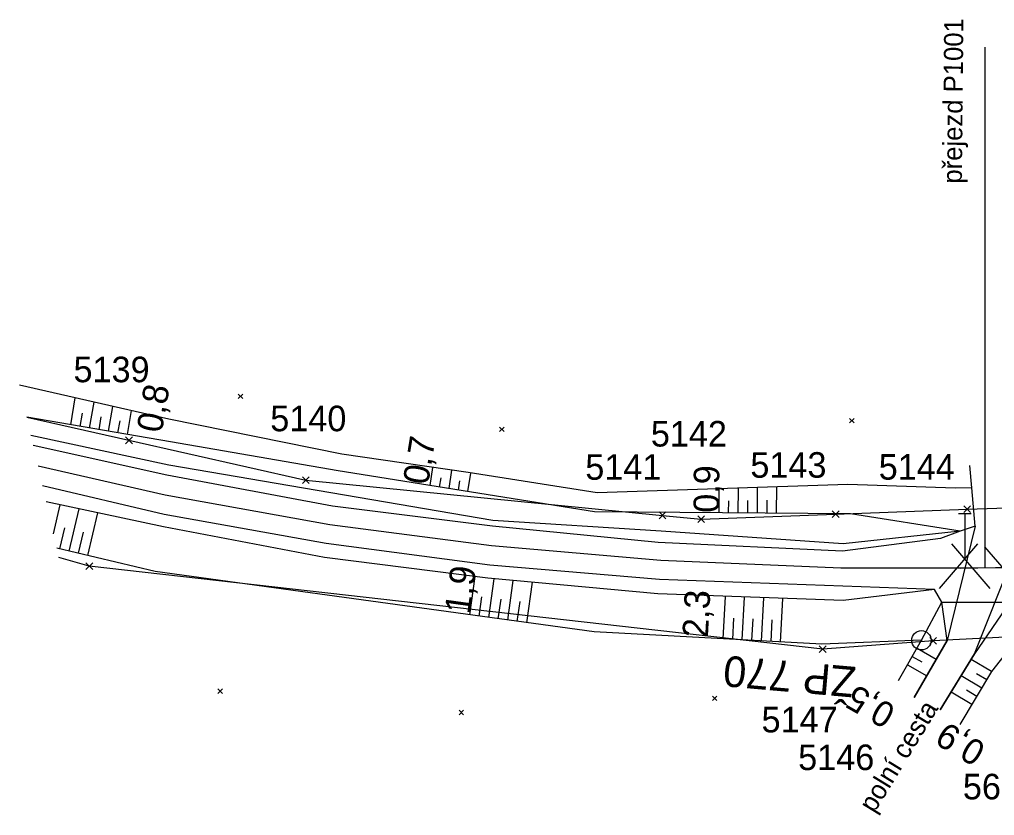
# Model space of a CAD drawing. Extents: x -805730 to -804640, y -1150889 to -1150366.
# Drawn here: x -805497.5 to -805421.3, y -1150709.2 to -1150646.9 of the extents above; entities that cross this region are included whole.
import ezdxf

# ---------------------------------------------------------------- set-up
doc = ezdxf.new("R2010")
doc.units = 0
for name, color, linetype in [('0381KM032-037P - Vrstva 1', 7, 'Continuous'), ('0381KM032-037P - Vrstva 19', 7, 'Continuous'), ('0381KM032-037P - Vrstva 4', 7, 'Continuous'), ('0381KM032-037P - Vrstva 48', 7, 'Continuous'), ('0381KM032-037P - Vrstva 49', 7, 'Continuous'), ('0381KM032-037P - Vrstva 51', 7, 'Continuous'), ('szdc - hran DP', 7, 'Continuous'), ('szdc - szdc_cislo', 7, 'Continuous'), ('szdc - szdc_krizek', 7, 'Continuous'), ('vyt_sit - stávající', 7, 'Continuous')]:
    doc.layers.add(name, color=color, linetype=linetype)

msp = doc.modelspace()

# ---------------------------------------------------------------- linework, layer by layer
at = {"layer": '0381KM032-037P - Vrstva 1'}
msp.add_lwpolyline([(-805364.564, -1150682.932), (-805366.036, -1150683.288), (-805378.364, -1150685.708), (-805390.905, -1150687.547), (-805419.964, -1150689.775), (-805423.956, -1150689.798), (-805433.29, -1150689.8), (-805447.38, -1150689.21), (-805460.61, -1150688.07), (-805473.24, -1150686.41), (-805486.12, -1150684.11), (-805496.07, -1150681.84)], dxfattribs=at)
at = {"layer": '0381KM032-037P - Vrstva 19'}
msp.add_line((-805425.408, -1150692.468), (-805420.073, -1150692.467), dxfattribs=at)
at = {"layer": '0381KM032-037P - Vrstva 4'}
for p, q in [((-805421.995, -1150689.771), (-805421.995, -1150649.075)), ((-805423.106, -1150685.551), (-805424.106, -1150685.551)), ((-805423.606, -1150685.551), (-805423.606, -1150689.051)), ((-805422.606, -1150687.901), (-805425.606, -1150691.401)), ((-805421.606, -1150691.401), (-805424.606, -1150687.901)), ((-805422.051, -1150688.145), (-805419.051, -1150691.645)), ((-805423.956, -1150689.798), (-805419.82, -1150689.74))]:
    msp.add_line(p, q, dxfattribs=at)
for points in [[(-805485.852, -1150681.76), (-805496.622, -1150679.425)], [(-805423.968, -1150686.92), (-805425.507, -1150687.489), (-805433.167, -1150688.486), (-805447.577, -1150687.793), (-805460.544, -1150686.523), (-805473.033, -1150684.969), (-805486.003, -1150682.535), (-805496.44, -1150680.221)], [(-805423.968, -1150686.92), (-805433.105, -1150687.911), (-805447.337, -1150686.911), (-805460.493, -1150686.088), (-805485.852, -1150681.76)], [(-805425.977, -1150691.468), (-805433.128, -1150691.222), (-805447.474, -1150690.705), (-805460.736, -1150689.572), (-805473.542, -1150687.873), (-805486.195, -1150685.623), (-805495.723, -1150683.361)], [(-805425.408, -1150692.468), (-805425.977, -1150691.468), (-805433.111, -1150692.346), (-805447.611, -1150691.816), (-805460.898, -1150690.591), (-805473.672, -1150688.976), (-805486.257, -1150686.575), (-805495.432, -1150684.633)]]:
    msp.add_lwpolyline(points, dxfattribs=at)
at = {"layer": '0381KM032-037P - Vrstva 48'}
for p, q in [((-805493.516, -1150678.599), (-805493.154, -1150676.492)), ((-805492.038, -1150678.853), (-805491.689, -1150676.823)), ((-805492.777, -1150678.726), (-805492.599, -1150677.692)), ((-805490.56, -1150679.107), (-805490.224, -1150677.155)), ((-805489.082, -1150679.361), (-805488.759, -1150677.486)), ((-805491.299, -1150678.98), (-805491.128, -1150677.985)), ((-805489.821, -1150679.234), (-805489.656, -1150678.277)), ((-805465.411, -1150683.343), (-805465.185, -1150681.938)), ((-805463.93, -1150683.582), (-805463.701, -1150682.155)), ((-805462.45, -1150683.82), (-805462.217, -1150682.374)), ((-805464.671, -1150683.462), (-805464.557, -1150682.754)), ((-805463.19, -1150683.701), (-805463.074, -1150682.982)), ((-805442.816, -1150685.486), (-805442.802, -1150683.603)), ((-805441.316, -1150685.497), (-805441.302, -1150683.554)), ((-805439.816, -1150685.508), (-805439.801, -1150683.505)), ((-805438.316, -1150685.519), (-805438.301, -1150683.457)), ((-805442.066, -1150685.491), (-805442.059, -1150684.535)), ((-805440.566, -1150685.502), (-805440.559, -1150684.516)), ((-805439.066, -1150685.514), (-805439.059, -1150684.497)), ((-805494.863, -1150687.121), (-805494.328, -1150684.869)), ((-805493.641, -1150688.469), (-805492.86, -1150685.181)), ((-805492.182, -1150688.816), (-805491.392, -1150685.492)), ((-805494.371, -1150688.296), (-805493.982, -1150686.66)), ((-805492.911, -1150688.642), (-805492.519, -1150686.989)), ((-805462.306, -1150693.457), (-805461.892, -1150690.465)), ((-805460.82, -1150693.663), (-805460.401, -1150690.636)), ((-805459.334, -1150693.868), (-805458.906, -1150690.775)), ((-805457.848, -1150694.074), (-805457.411, -1150690.913)), ((-805461.563, -1150693.56), (-805461.355, -1150692.059)), ((-805460.077, -1150693.766), (-805459.865, -1150692.235)), ((-805442.496, -1150695.345), (-805442.316, -1150692.013)), ((-805440.998, -1150695.425), (-805440.817, -1150692.068)), ((-805439.5, -1150695.506), (-805439.318, -1150692.123)), ((-805438.003, -1150695.587), (-805437.819, -1150692.178)), ((-805458.591, -1150693.971), (-805458.375, -1150692.407)), ((-805441.747, -1150695.385), (-805441.657, -1150693.713)), ((-805440.249, -1150695.466), (-805440.158, -1150693.781)), ((-805438.751, -1150695.546), (-805438.66, -1150693.848)), ((-805427.337, -1150696.056), (-805425.831, -1150696.919)), ((-805427.71, -1150696.707), (-805426.958, -1150697.138)), ((-805428.083, -1150697.358), (-805426.58, -1150698.219)), ((-805421.505, -1150697.899), (-805423.112, -1150696.945)), ((-805422.272, -1150699.189), (-805423.895, -1150698.224)), ((-805421.889, -1150698.544), (-805422.696, -1150698.064)), ((-805423.038, -1150700.478), (-805424.678, -1150699.504)), ((-805422.655, -1150699.834), (-805423.471, -1150699.349))]:
    msp.add_line(p, q, dxfattribs=at)
at = {"layer": '0381KM032-037P - Vrstva 49'}
for p, q in [((-805480.059, -1150676.544), (-805480.413, -1150676.19)), ((-805480.059, -1150676.19), (-805480.413, -1150676.544)), ((-805432.255, -1150678.453), (-805432.609, -1150678.099)), ((-805432.255, -1150678.099), (-805432.609, -1150678.453)), ((-805459.618, -1150679.124), (-805459.972, -1150678.77)), ((-805459.618, -1150678.77), (-805459.972, -1150679.124)), ((-805426.992, -1150695.453), (-805425.408, -1150692.468)), ((-805481.651, -1150699.609), (-805482.005, -1150699.255)), ((-805481.651, -1150699.255), (-805482.005, -1150699.609)), ((-805442.98, -1150700.163), (-805443.334, -1150699.809)), ((-805442.98, -1150699.809), (-805443.334, -1150700.163)), ((-805462.79, -1150701.281), (-805463.144, -1150700.927)), ((-805462.79, -1150700.927), (-805463.144, -1150701.281))]:
    msp.add_line(p, q, dxfattribs=at)
for points in [[(-805424.361, -1150683.566), (-805432.744, -1150683.276), (-805452.346, -1150683.913), (-805462.434, -1150682.34), (-805472.303, -1150680.897), (-805485.837, -1150678.147), (-805497.518, -1150675.505)], [(-805422.802, -1150686.532), (-805423.968, -1150686.92), (-805432.545, -1150685.563), (-805452.563, -1150685.412), (-805472.604, -1150682.185), (-805485.723, -1150679.939), (-805496.946, -1150678.009)], [(-805423.968, -1150686.92), (-805433.105, -1150687.911), (-805447.337, -1150686.911), (-805460.493, -1150686.088), (-805485.852, -1150681.76), (-805496.622, -1150679.425)], [(-805422.802, -1150686.532), (-805423.053, -1150683.538), (-805424.361, -1150683.566)], [(-805425.408, -1150692.468), (-805425.977, -1150691.468), (-805433.111, -1150692.346), (-805447.611, -1150691.816), (-805460.898, -1150690.591), (-805473.672, -1150688.976), (-805486.257, -1150686.575), (-805495.432, -1150684.633)], [(-805428.796, -1150698.607), (-805426.992, -1150695.453), (-805434.791, -1150695.763), (-805452.595, -1150694.797), (-805474.791, -1150691.727), (-805486.897, -1150690.069), (-805494.608, -1150688.237)], [(-805427.559, -1150699.915), (-805424.986, -1150695.461), (-805425.408, -1150692.468)], [(-805420.073, -1150692.467), (-805422.844, -1150696.501), (-805425.524, -1150700.881)], [(-805423.96, -1150702.025), (-805421.499, -1150697.887), (-805419.738, -1150695.668)]]:
    msp.add_lwpolyline(points, dxfattribs=at)
at = {"layer": '0381KM032-037P - Vrstva 51'}
for points in [[(-805425.524, -1150700.881), (-805422.844, -1150696.501), (-805419.834, -1150688.974), (-805419.997, -1150686.968), (-805420.48, -1150681.602)], [(-805422.802, -1150686.532), (-805423.053, -1150683.538), (-805423.2, -1150681.793)], [(-805422.802, -1150686.532), (-805424.986, -1150695.461), (-805427.559, -1150699.915)]]:
    msp.add_lwpolyline(points, dxfattribs=at)
at = {"layer": 'szdc - hran DP'}
for p, q in [((-805496.945, -1150678.011), (-805488.96, -1150679.81)), ((-805488.96, -1150679.81), (-805475.13, -1150682.93)), ((-805475.13, -1150682.93), (-805447.24, -1150685.68)), ((-805433.7, -1150685.59), (-805423.42, -1150685.2)), ((-805423.42, -1150685.2), (-805418.81, -1150685.03)), ((-805447.24, -1150685.68), (-805444.22, -1150685.98)), ((-805444.22, -1150685.98), (-805433.7, -1150685.59)), ((-805492.06, -1150689.65), (-805494.44, -1150688.972)), ((-805434.71, -1150696.14), (-805492.06, -1150689.65)), ((-805420.42, -1150695.2), (-805426.08, -1150695.49)), ((-805426.08, -1150695.49), (-805434.71, -1150696.14))]:
    msp.add_line(p, q, dxfattribs=at)
at = {"layer": 'szdc - szdc_krizek'}
for p, q in [((-805488.695, -1150680.075), (-805489.226, -1150679.545)), ((-805489.226, -1150680.075), (-805488.695, -1150679.545)), ((-805474.865, -1150683.195), (-805475.396, -1150682.665)), ((-805475.396, -1150683.195), (-805474.865, -1150682.665)), ((-805446.975, -1150685.945), (-805447.506, -1150685.415)), ((-805447.506, -1150685.945), (-805446.975, -1150685.415)), ((-805433.435, -1150685.855), (-805433.966, -1150685.325)), ((-805433.966, -1150685.855), (-805433.435, -1150685.325)), ((-805423.155, -1150685.465), (-805423.686, -1150684.935)), ((-805423.686, -1150685.465), (-805423.155, -1150684.935)), ((-805443.955, -1150686.245), (-805444.486, -1150685.715)), ((-805444.486, -1150686.245), (-805443.955, -1150685.715)), ((-805491.795, -1150689.915), (-805492.326, -1150689.385)), ((-805492.326, -1150689.915), (-805491.795, -1150689.385)), ((-805425.815, -1150695.755), (-805426.346, -1150695.225)), ((-805426.346, -1150695.755), (-805425.815, -1150695.225)), ((-805434.445, -1150696.405), (-805434.976, -1150695.875)), ((-805434.976, -1150696.405), (-805434.445, -1150695.875))]:
    msp.add_line(p, q, dxfattribs=at)
at = {"layer": 'vyt_sit - stávající'}
msp.add_line((-805427.042, -1150695.453), (-805426.942, -1150695.453), dxfattribs=at)
msp.add_circle((-805426.992, -1150695.453), 0.756, dxfattribs=at)

# ---------------------------------------------------------------- texts
at = {"layer": '0381KM032-037P - Vrstva 4'}
msp.add_text('přejezd P1001', height=1.5, rotation=89.45469, dxfattribs=at).set_placement((-805423.832, -1150659.74))
at = {"layer": '0381KM032-037P - Vrstva 48'}
for s, rotation, p in [('0,8', 80.24135, (-805486.401, -1150679.289)), ('0,7', 80.85275, (-805465.576, -1150683.349)), ('0,9', 89.56781, (-805442.816, -1150685.486)), ('1,9', 82.1252, (-805462.306, -1150693.457)), ('2,3', 86.89432, (-805443.693, -1150695.28)), ('0,5', 150.22776, (-805428.88, -1150700.694)), ('0,9', 149.25871, (-805421.832, -1150703.661))]:
    msp.add_text(s, height=2, rotation=rotation, dxfattribs=at).set_placement(p)
at = {"layer": '0381KM032-037P - Vrstva 51'}
msp.add_text('polní cesta', height=1.5, rotation=58.5387, dxfattribs=at).set_placement((-805430.69, -1150709.032))
at = {"layer": 'szdc - szdc_cislo'}
for s, p in [('5139', (-805493.294, -1150675.269)), ('5140', (-805477.908, -1150679.103)), ('5142', (-805448.15, -1150680.298)), ('5141', (-805453.275, -1150682.896)), ('5143', (-805440.367, -1150682.738)), ('5144', (-805430.333, -1150682.887)), ('5147', (-805439.494, -1150702.654)), ('5146', (-805436.631, -1150705.602)), ('5601', (-805423.75, -1150707.89))]:
    msp.add_text(s, height=2, dxfattribs=at).set_placement(p)
at = {"layer": 'vyt_sit - stávající'}
msp.add_text('ŽP 770', height=2.4, rotation=175, dxfattribs=at).set_placement((-805432.049, -1150697.54))

doc.saveas('drawing.dxf')
